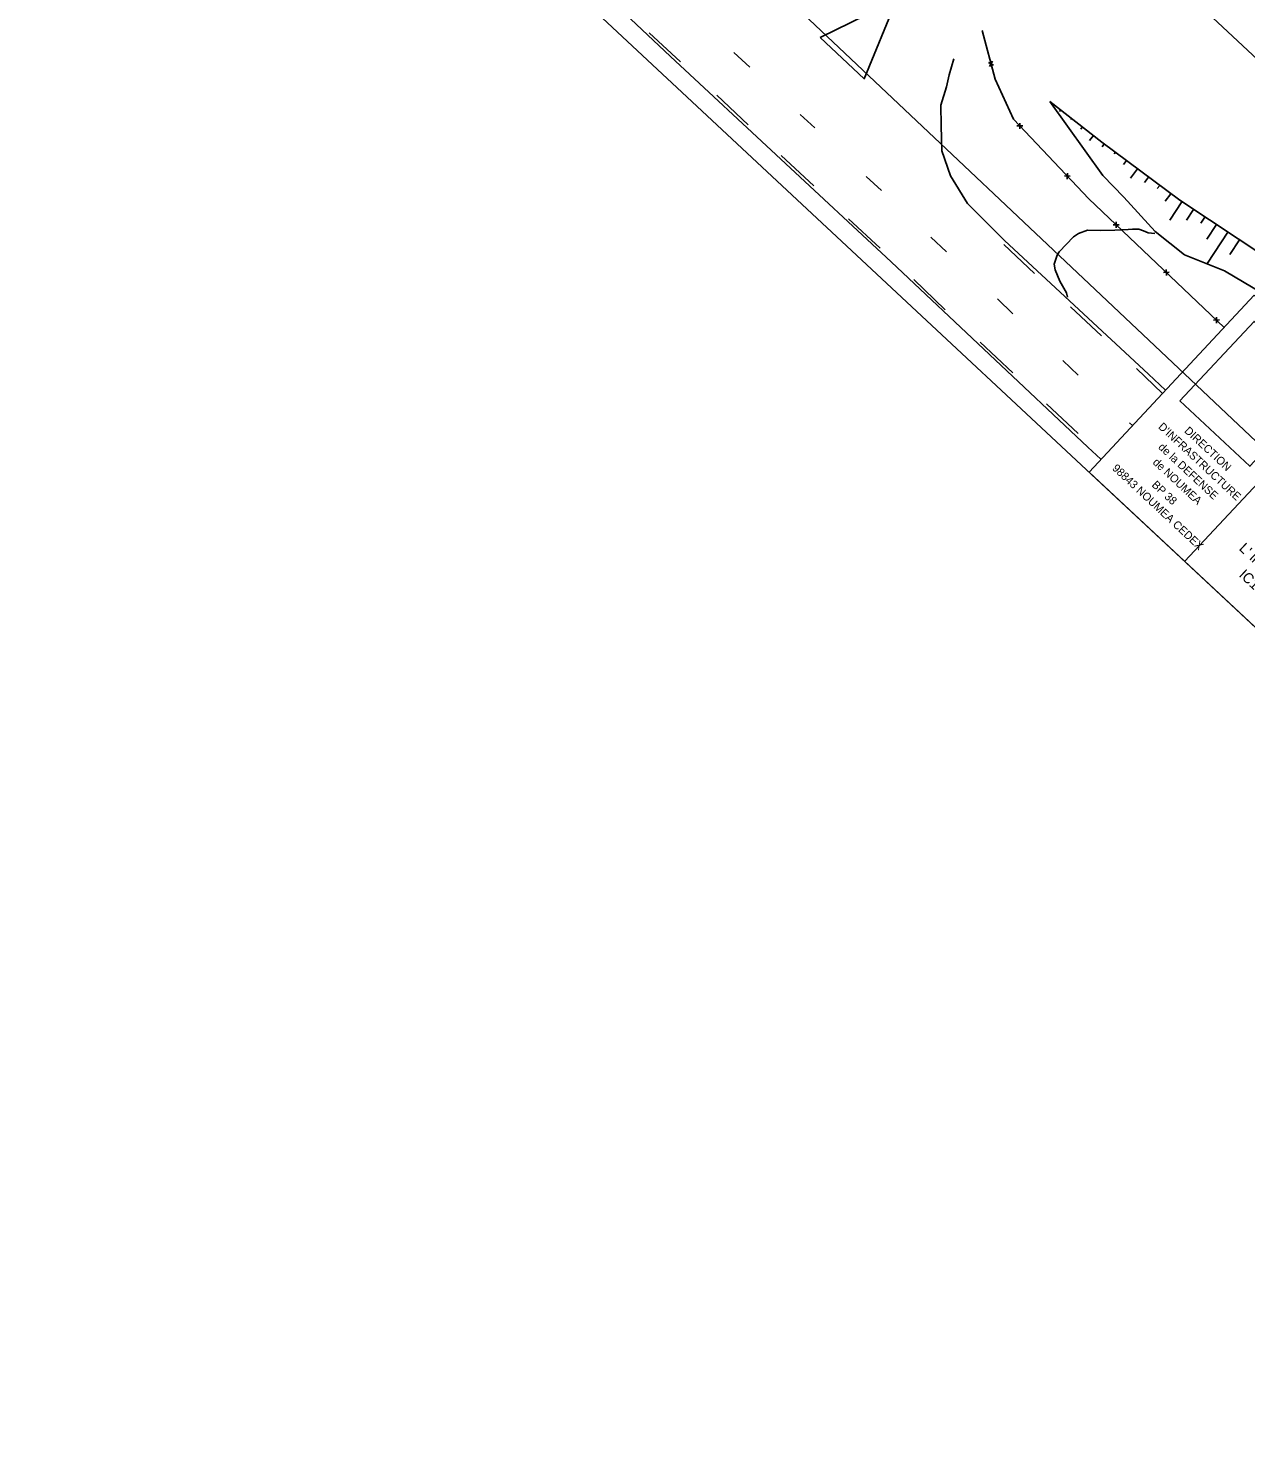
# Model space of a CAD drawing. Extents: x 343997 to 344255, y 298512 to 298767.
# Drawn here: x 343997.3 to 344085.4, y 298518.2 to 298621.1 of the extents above; entities that cross this region are included whole.
import ezdxf

# ---------------------------------------------------------------- set-up
doc = ezdxf.new("R2010")
doc.units = 0
for name, color, linetype in [('DH_CADRE -CARTOUCHE', 7, 'Continuous'), ('IMM_VOIRIE VOIE FERREE', 7, 'Continuous'), ('PS_HATCH', 7, 'Continuous'), ('PS_KOTE', 7, 'Continuous'), ('PS_OBJECT', 7, 'Continuous'), ('PS_PLATE', 7, 'Continuous'), ('PS_WELD', 7, 'Continuous'), ('RES_TELEPHONE SOUTERRAIN', 7, 'Continuous')]:
    doc.layers.add(name, color=color, linetype=linetype)

msp = doc.modelspace()

# ---------------------------------------------------------------- linework, layer by layer
at = {"layer": 'DH_CADRE -CARTOUCHE'}
msp.add_line((344092.93, 298595.37), (344080.99, 298582.58), dxfattribs=at)
for points in [[(343997.31, 298660.67), (344147.18, 298520.81), (344245.09, 298625.72), (344095.21, 298765.59)], [(344086.01, 298601.83), (344159.12, 298533.6), (344147.18, 298520.81), (344074.07, 298589.03)], [(344080.64, 298594.19), (344085.71, 298589.46), (344091.07, 298595.21), (344086.01, 298599.94)]]:
    msp.add_lwpolyline(points, close=True, dxfattribs=at)
at = {"layer": 'IMM_VOIRIE VOIE FERREE'}
for p, q in [((344079.38, 298594.72), (344077.49, 298596.53)), ((344077.21, 298592.4), (344076.99, 298592.6))]:
    msp.add_line(p, q, dxfattribs=at)
for points in [[(344074.93, 298589.96), (344073.98, 298590.84), (344059.74, 298604.25), (344043.78, 298619.11), (344027.34, 298634.6), (344011.46, 298649.63), (344000.23, 298660.03)], [(344042.24, 298620.83), (344044.51, 298618.72)], [(344049.51, 298618.33), (344048.35, 298619.39)], [(344079.6, 298594.96), (344078.37, 298596.11), (344067.95, 298605.78), (344065.27, 298608.47), (344064.03, 298610.47), (344063.42, 298612.29), (344063.37, 298614.09), (344063.35, 298615.59), (344063.74, 298616.9), (344063.95, 298617.79), (344064.28, 298618.94)], [(344047.12, 298616.31), (344049.39, 298614.15)], [(344054.22, 298613.94), (344053.16, 298614.92)], [(344051.79, 298611.94), (344054.15, 298609.75)], [(344059.04, 298609.41), (344057.93, 298610.43)], [(344056.67, 298607.35), (344058.95, 298605.23)], [(344063.76, 298604.96), (344062.62, 298606.03)], [(344070.12, 298603.4), (344067.9, 298605.51)], [(344061.38, 298602.96), (344063.66, 298600.78)], [(344068.56, 298600.49), (344067.43, 298601.57)], [(344074.96, 298598.89), (344072.72, 298601)], [(344066.19, 298598.43), (344068.56, 298596.22)], [(344073.27, 298596.05), (344072.18, 298597.11)], [(344070.99, 298593.96), (344073.28, 298591.82)]]:
    msp.add_lwpolyline(points, dxfattribs=at)
at = {"layer": 'PS_HATCH'}
msp.add_lwpolyline([(344078.82, 298606.3), (344078.34, 298606.35), (344078.01, 298606.48), (344077.67, 298606.61), (344077.21, 298606.61), (344076.9, 298606.58), (344075.94, 298606.55), (344074.91, 298606.51), (344073.95, 298606.53), (344073.31, 298606.3), (344072.95, 298606.06), (344071.91, 298604.98), (344071.77, 298604.74), (344071.55, 298604.08), (344071.61, 298603.68), (344071.96, 298602.85), (344072.43, 298602.01), (344072.51, 298601.69)], dxfattribs=at)
at = {"layer": 'PS_KOTE'}
msp.add_lwpolyline([(344054.6, 298620.49), (344057.8, 298617.5), (344060.14, 298623.19)], close=True, dxfattribs=at)
at = {"layer": 'PS_OBJECT'}
for p, q in [((344072.01, 298615.23), (344071.93, 298615.12)), ((344072.8, 298614.62), (344072.75, 298614.55)), ((344073.59, 298614.01), (344073.47, 298613.85)), ((344074.38, 298613.39), (344074.1, 298613.03)), ((344075.17, 298612.78), (344075.01, 298612.57)), ((344075.97, 298612.18), (344075.88, 298612.06)), ((344076.77, 298611.58), (344076.56, 298611.29)), ((344077.58, 298610.98), (344077.07, 298610.3)), ((344078.38, 298610.38), (344078.08, 298609.99)), ((344079.18, 298609.78), (344079, 298609.55)), ((344079.98, 298609.18), (344079.57, 298608.64)), ((344080.78, 298608.59), (344079.91, 298607.27)), ((344081.62, 298608.04), (344081.11, 298607.27)), ((344082.45, 298607.49), (344082.16, 298607.04)), ((344083.29, 298606.94), (344082.59, 298605.88)), ((344084.12, 298606.39), (344082.65, 298604.16)), ((344084.96, 298605.84), (344084.26, 298604.78))]:
    msp.add_line(p, q, dxfattribs=at)
for points in [[(344071.22, 298615.85), (344074.99, 298612.91), (344080.63, 298608.7), (344087, 298604.49), (344090.87, 298601.92), (344093.45, 298599.63), (344095.24, 298597.27), (344096.48, 298594.9), (344098.44, 298592.75), (344100, 298591.22), (344100.91, 298590.14)], [(344091.18, 298597), (344089.45, 298599.15), (344086.59, 298601.97), (344083.86, 298603.59), (344080.98, 298604.75), (344078.86, 298606.45), (344076.59, 298608.92), (344075.06, 298610.5), (344071.22, 298615.85)]]:
    msp.add_lwpolyline(points, dxfattribs=at)
at = {"layer": 'PS_PLATE'}
msp.add_lwpolyline([(344092.72, 298634.81), (344105.19, 298623.15), (344094.24, 298611.44), (344080.1, 298624.66), (344082.36, 298627.12), (344084.04, 298625.58), (344092.72, 298634.81)], dxfattribs=at)
at = {"layer": 'PS_WELD'}
for p, q in [((344066.8, 298618.68), (344067.16, 298618.47)), ((344067.09, 298618.76), (344066.87, 298618.39)), ((344068.84, 298614.09), (344069.27, 298614.08)), ((344069.06, 298614.29), (344069.05, 298613.87)), ((344072.28, 298610.46), (344072.71, 298610.45)), ((344072.5, 298610.67), (344072.49, 298610.24)), ((344075.82, 298606.92), (344076.25, 298606.93)), ((344076.03, 298607.14), (344076.04, 298606.71)), ((344079.66, 298603.69), (344079.67, 298603.27)), ((344079.45, 298603.48), (344079.87, 298603.49)), ((344083.07, 298600.03), (344083.5, 298600.04)), ((344083.28, 298600.25), (344083.29, 298599.82))]:
    msp.add_line(p, q, dxfattribs=at)
msp.add_lwpolyline([(344066.32, 298620.99), (344067.28, 298617.46), (344068.6, 298614.56), (344074.05, 298608.81), (344083.84, 298599.5)], dxfattribs=at)
at = {"layer": 'RES_TELEPHONE SOUTERRAIN'}
msp.add_lwpolyline([(344006.37, 298666.61), (344159.5, 298522.02), (344160.82, 298520.82), (344163.6, 298518.23)], dxfattribs=at)

# ---------------------------------------------------------------- texts
at = {"layer": 'DH_CADRE -CARTOUCHE'}
for s, height, p in [("D'INFRASTRUCTURE", 0.5789, (344079.03, 298592.25)), ('DIRECTION', 0.579, (344080.92, 298591.96)), ('de la DEFENSE', 0.5789, (344079.03, 298590.78)), ('98843 NOUMEA CEDEX', 0.5789, (344075.7, 298589.25)), ('de NOUMEA', 0.579, (344078.63, 298589.68)), ('BP 38', 0.579, (344078.56, 298588.05)), ("L' ingénieur en chef de 1ère classe", 0.75, (344084.87, 298583.44)), ('IC1MI Dominique LANCIEN', 0.75, (344084.87, 298581.53))]:
    msp.add_text(s, height=height, rotation=316.9784, dxfattribs=at).set_placement(p)

doc.saveas('drawing.dxf')
